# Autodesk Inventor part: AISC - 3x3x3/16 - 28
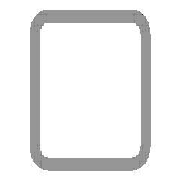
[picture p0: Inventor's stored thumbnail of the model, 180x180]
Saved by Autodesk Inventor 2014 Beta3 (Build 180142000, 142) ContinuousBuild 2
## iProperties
Created: 2011-01
Part Number: AISC - 3x3x3/16 - 28
Material: Steel, Mild
Description: Tube
Document SubType Name: Modeling
Standard: ANSI
Designer: Beta-8540w
Standards Organization: ANSI
Language: en-US
Size Designation: 3x3x3/16
Categories: <MemberInstance><Categories><Category DisplayName="Structural Shapes" InternalName="089c4875-fa83-4c05-b084-43b9cc11f5ed" Mnemonic="GRDR"><CategoryParameter Dis
Stock Number: 3x3x3/16
Density: 7.86 g/cm^3
Appearance: Steel
IsCustomPart: 1
_CCFamilyMember: 9
_CCFamilyDisplayName: ANSI AISC (Square) - Tube
_FrameMemberDoc: Frame Member File
_Version: 15.0.0
_GetPNFromCC: 1
G_L: 28.000 in
G_W: 3.000 in
G_H: 3.000 in
Author: Beta-8540w
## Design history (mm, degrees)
node "Start plane"
node "End plane"
sketch "Sketch"
  geometry: L1 (-38.1, -28.575)-(-38.1, 28.575); L2 (-28.575, 38.1)-(28.575, 38.1); L3 (38.1, 28.575)-(38.1, -28.575); L4 (28.575, -38.1)-(-28.575, -38.1); L5 (-28.575, 33.337)-(28.575, 33.338); L6 (33.338, 28.575)-(33.338, -28.575); L7 (28.575, -33.337)-(-28.575, -33.338); L8 (-33.338, -28.575)-(-33.338, 28.575); L9 (0, 56.102)-(0, -56.102) reference; L10 (-56.102, 0)-(56.102, 0) reference; A1 r 9.525 centre (-28.575, -28.575) between (-38.1, -28.575) and (-28.575, -38.1); A2 r 9.525 centre (-28.575, 28.575) between (-28.575, 38.1) and (-38.1, 28.575); A3 r 9.525 centre (28.575, 28.575) between (38.1, 28.575) and (28.575, 38.1); A4 r 9.525 centre (28.575, -28.575) between (28.575, -38.1) and (38.1, -28.575); A5 r 4.763 centre (-28.575, 28.575) between (-28.575, 33.337) and (-33.338, 28.575); A6 r 4.763 centre (28.575, 28.575) between (33.338, 28.575) and (28.575, 33.338); A7 r 4.763 centre (28.575, -28.575) between (28.575, -33.337) and (33.338, -28.575); A8 r 4.763 centre (-28.575, -28.575) between (-33.338, -28.575) and (-28.575, -33.338)
  constraints: 16 end point, 16 point on circle, 8 centre point, 8 tangent, 4 parallel, 3 equal radius, 2 perpendicular, 7 other
  dimensions: "d10" = 76.2 distance between parallel lines of L2 L4 (= G_H); "d11" = 76.2 distance between parallel lines of L1 L3 (= G_W); "d12" = 4.7625 distance between parallel lines of L3 L6 (= G_T); "d15" = 38.1 distance between parallel lines of L2 L10 (= 0.5 x d10); "d16" = 38.1 distance between parallel lines of L9 L3 (= 0.5 x d11); "d17" = 9.525 radius of A1 (= G_IR)
extrude "Body" new body sketch "Sketch" stored distance "d3" = 711.2 (= G_L); taper "d4" = 0 deg
node "Driven Length"
  sketch "Sketch3"
    geometry: L1 (0, 0)-(10, 0) reference
    constraints: 2 end point, 1 horizontal
  workplane "Work Plane3"
  sketch "Sketch4"
    geometry: L1 (-2, 0)-(12, 0) reference; L2 (-2, 711.2)-(12, 711.2) reference
    dimensions: "d19" = 711.2 distance between parallel lines of L1 L2 (derived)
body "Solid1"
other parameters: "G_W" = 76.2 [user parameter; used in 1 equation term], "G_H" = 76.2 [user parameter; used in 1 equation term], "G_T" = 4.7625 [user parameter; used in 1 equation term], "G_IR" = 9.525 [user parameter; used in 1 equation term], "G_L" = 711.2 (= d19) [user parameter; used in 1 equation term], "G_OFFSET_START" = 0 [user parameter; used in 1 equation term], "G_OFFSET_END" = 0 [user parameter; used in 1 equation term], "d13" = 0 (computed from G_OFFSET_START), "d14" = 711.2 (= G_OFFSET_END + B_L), "B_L" = 711.2 [user parameter; used in 1 equation term], "d18" = 90 deg
